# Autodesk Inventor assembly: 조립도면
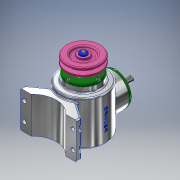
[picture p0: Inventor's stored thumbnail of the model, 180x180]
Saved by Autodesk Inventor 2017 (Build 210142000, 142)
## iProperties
Part Number: 조립도면
Material: 일반
Document SubType Name: Assembly
Designer: MRC
Author: MRC
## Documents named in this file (17)
- C:\Users\MRC\Desktop\730108V1003\조립도면.iam
- C:\Users\MRC\Desktop\730108V1003\V-벨트풀리.ipt
- C:\Users\MRC\Desktop\730108V1003\메인 베벨기어.ipt
- C:\Users\MRC\Desktop\730108V1003\메인 축.ipt
- 메인 축.ipt
- C:\Users\MRC\Desktop\730108V1003\베어링 6203.ipt
- C:\Users\MRC\Desktop\730108V1003\본체.ipt
- C:\Users\MRC\Desktop\730108V1003\볼트 M4 x 10.ipt
- C:\Users\MRC\Desktop\730108V1003\서브 베벨기어.ipt
- C:\Users\MRC\Desktop\730108V1003\서브 축.ipt
- 서브 축.ipt
- C:\Users\MRC\Desktop\730108V1003\오일실 17 x 32 x 8.ipt
- C:\Users\MRC\Desktop\730108V1003\와셔 4 x 16.ipt
- C:\Users\MRC\Desktop\730108V1003\육각볼트 M4 x 8.ipt
- C:\Users\MRC\Desktop\730108V1003\커버.ipt
- C:\Users\MRC\Desktop\730108V1003\키 4 x 4 x 14.ipt
- C:\Users\MRC\Desktop\730108V1003\키 5 x 5 x 14.ipt
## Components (1 placed, 1 different names)
1. V-벨트풀리:1
